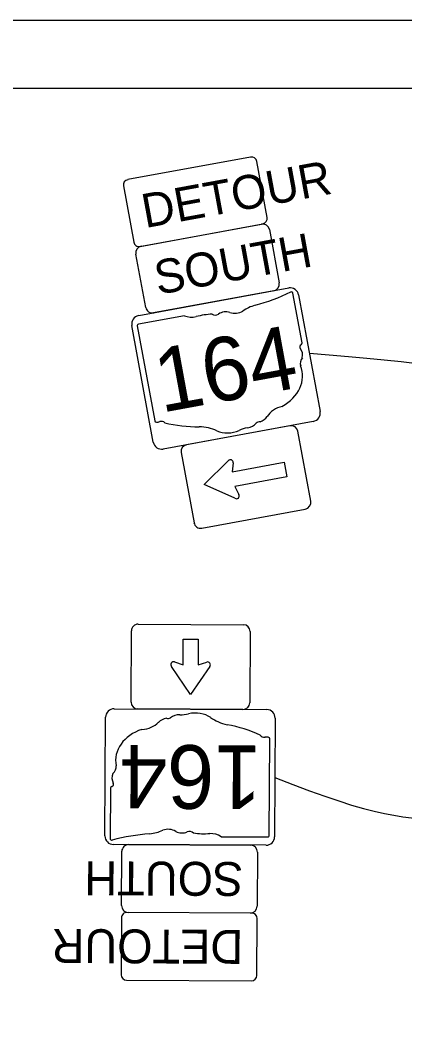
# Model space of a CAD drawing. Extents: x -202 to 1556, y 0 to 676.
# Drawn here: x 356.1 to 412.8, y 289.7 to 440 of the extents above; entities that cross this region are included whole.
import ezdxf

# ---------------------------------------------------------------- set-up
doc = ezdxf.new("R2010")
doc.units = 0
for name, color, linetype in [('GM_X_Minor_Lake', 7, 'Continuous'), ('GM_X_Minor_Lake_Text', 7, 'Continuous'), ('SH_Border', 7, 'Continuous'), ('SH_Cut_Line', 7, 'Continuous'), ('SH_Data', 7, 'Continuous')]:
    doc.layers.add(name, color=color, linetype=linetype)

msp = doc.modelspace()

# ---------------------------------------------------------------- linework, layer by layer
at = {"layer": 'GM_X_Minor_Lake'}
for p, q in [((373.97, 406.72), (391.67, 409.98)), ((392.84, 409.17), (394.29, 401.31)), ((374.62, 397.69), (373.17, 405.56)), ((393.48, 400.14), (375.78, 396.89)), ((397.66, 392.45), (396.31, 399.77)), ((380.31, 396.47), (373.55, 395.23)), ((373.37, 394.95), (375.95, 380.95)), ((397.66, 392.45), (397.66, 392.45)), ((373.51, 350.99), (389.01, 350.91)), ((372.45, 339.5), (372.5, 350)), ((380.14, 345.02), (380.15, 348.77)), ((380.15, 348.77), (382.34, 348.76)), ((382.34, 348.76), (382.32, 345.01)), ((390, 349.91), (389.95, 339.41)), ((381.21, 340.64), (378.43, 344.74)), ((378.85, 345.43), (380.14, 345.02)), ((384.07, 344.77), (381.21, 340.64)), ((382.32, 345.01), (383.61, 345.4)), ((388.94, 338.41), (373.44, 338.5)), ((392.82, 319.87), (392.89, 334.1)), ((369.42, 326.84), (369.38, 319.39)), ((369.42, 326.83), (369.42, 326.84)), ((385.72, 319.66), (392.59, 319.62)), ((371.04, 309.51), (371.09, 317.51)), ((372.09, 318.5), (390.09, 318.41)), ((391.09, 317.4), (391.04, 309.4)), ((390.04, 308.41), (372.04, 308.5))]:
    msp.add_line(p, q, dxfattribs=at)
for points in [[(390.06, 419.85), (371.96, 416.52)], [(392.51, 410.94), (390.99, 419.21)], [(371.32, 415.59), (372.84, 407.33)], [(373.77, 406.68), (391.87, 410.01)], [(373.57, 396.48), (395.7, 400.55)], [(397.15, 399.55), (400.32, 382.33)], [(375.73, 377.81), (372.56, 395.02)], [(399.31, 380.88), (377.19, 376.81)], [(369.94, 338.51), (392.44, 338.4)], [(368.6, 319.77), (368.69, 337.27)], [(393.69, 337.14), (393.6, 319.64)], [(392.34, 318.4), (369.84, 318.51)], [(390.24, 308.41), (371.84, 308.5)], [(371.03, 307.71), (370.99, 299.31)], [(390.99, 299.2), (391.03, 307.6)], [(371.79, 298.5), (390.19, 298.41)]]:
    msp.add_lwpolyline(points, dxfattribs=at)
for centre, radius, start, end in [((390.21, 419.06), 0.8, 10.4238, 100.4238), ((372.11, 415.73), 0.8, 100.4238, 190.4238), ((391.73, 410.8), 0.8, 280.4238, 10.4238), ((391.85, 408.99), 1, 10.4238, 100.4238), ((373.63, 407.47), 0.8, 190.4238, 280.4238), ((374.15, 405.74), 1, 100.4238, 190.4238), ((393.3, 401.13), 1, 280.4238, 10.4238), ((395.92, 399.32), 1.25, 10.4238, 100.4238), ((375.6, 397.87), 1, 190.4238, 280.4238), ((373.79, 395.25), 1.25, 100.4238, 190.4238), ((399.09, 382.11), 1.25, 280.4238, 10.4238), ((376.96, 378.04), 1.25, 190.4238, 280.4238), ((373.5, 349.99), 1, 89.7036, 179.7036), ((389, 349.91), 1, 359.7036, 89.7036), ((378.73, 345.03), 0.417, 72.499, 224.7132), ((383.73, 345), 0.417, 325.1148, 106.9082), ((369.94, 337.26), 1.25, 89.7036, 179.7036), ((373.45, 339.49), 1, 179.7036, 269.7036), ((388.95, 339.41), 1, 269.7036, 359.7036), ((392.44, 337.15), 1.25, 359.7036, 89.7036), ((369.85, 319.76), 1.25, 179.7036, 269.7036), ((392.35, 319.65), 1.25, 269.7036, 359.7036), ((372.09, 317.5), 1, 89.7036, 179.7036), ((390.09, 317.41), 1, 359.7036, 89.7036), ((371.83, 307.7), 0.8, 89.7036, 179.7036), ((372.04, 309.5), 1, 179.7036, 269.7036), ((390.04, 309.41), 1, 269.7036, 359.7036), ((390.23, 307.61), 0.8, 359.7036, 89.7036), ((371.79, 299.3), 0.8, 179.7036, 269.7036), ((390.19, 299.21), 0.8, 269.7036, 359.7036)]:
    msp.add_arc(centre, radius, start, end, dxfattribs=at)
for centre, major_axis, start_param, end_param in [((384.66, 417), (24.44, 4.5), 4.814394, 5.042369), ((396.05, 399.76), (0.257, 0.047), 6.141152, 7.989035), ((384.22, 389.07), (9.3, 1.71), 1.404758, 1.657858), ((384.91, 397.17), (0.747, 0.137), 3.836095, 5.185415), ((386.3, 395.76), (1.55, 0.29), 0.950623, 2.079405), ((387.9, 398.35), (1.87, 0.34), 4.081561, 5.145723), ((392.07, 394.22), (4.92, 0.9), 1.699011, 2.107814), ((373.63, 395.02), (0.267, 0.049), 1.712693, 3.28349), ((381.61, 398.39), (2.59, 0.48), 4.042523, 4.731795), ((397.7, 391.9), (0.397, 0.073), 1.883978, 3.671073), ((397.39, 392.37), (0.275, 0.051), 5.05454, 6.418171), ((395.34, 390.51), (2.38, 0.44), 5.934695, 6.695948), ((399.14, 389.56), (1.73, 0.32), 2.387724, 3.262537), ((391.55, 387.2), (6.11, 1.12), 5.101752, 6.440018), ((395.46, 380.48), (3.35, 0.62), 1.647645, 2.488434), ((376.22, 380.97), (0.269, 0.05), 3.00124, 4.508301), ((376, 382.41), (2.06, 0.38), 4.665946, 4.897461), ((376.82, 380.28), (0.741, 0.136), 0.519207, 1.627899), ((383.87, 394.57), (17.65, 3.25), 4.195997, 4.488961), ((389.38, 381.43), (1.87, 0.34), 4.691044, 5.507374), ((391.32, 380.39), (0.526, 0.097), 1.147584, 2.315152), ((390.74, 382.27), (1.98, 0.36), 4.937069, 5.64225), ((381.93, 375.55), (5.52, 1.02), 0.823519, 1.323587), ((386.91, 382.06), (3.5, 0.64), 4.026481, 4.996735), ((389.82, 377.59), (2.88, 0.53), 1.495662, 1.94098), ((378.11, 335.55), (-2.01, 0.01), 4.937069, 5.64225), ((377.89, 337.51), (-0.535, 0.003), 1.147584, 2.315152), ((379.6, 336.12), (-1.9, 0.01), 4.691044, 5.507374), ((379.88, 339.98), (-2.93, 0.02), 1.495662, 1.94098), ((381.92, 335.05), (-3.56, 0.02), 4.026481, 4.996735), ((388.02, 340.52), (-5.62, 0.03), 0.823519, 1.323587), ((376.39, 330.86), (-6.22, 0.03), 5.101752, 6.440018), ((373.81, 338.19), (-3.4, 0.02), 1.647645, 2.488434), ((382.57, 322.19), (-17.95, 0.09), 4.195997, 4.488961), ((392.16, 334.92), (-0.754, 0.004), 0.519207, 1.627899), ((392.57, 332.67), (-2.09, 0.01), 4.665946, 4.897461), ((392.62, 334.13), (-0.274, 0.001), 3.00124, 4.508301), ((368.5, 329.96), (-1.76, 0.01), 2.387724, 3.262537), ((372.05, 328.31), (-2.42, 0.01), 5.934695, 6.695948), ((369.69, 326.86), (-0.279, 0.001), 5.05454, 6.418171), ((369.48, 327.38), (-0.404, 0.002), 1.883978, 3.671073), ((377.63, 300.3), (-24.85, 0.13), 4.814394, 5.042369), ((374.58, 324.06), (-5, 0.03), 1.699011, 2.107814), ((377.91, 319.23), (-1.9, 0.01), 4.081561, 5.145723), ((379.96, 321.47), (-1.58, 0.01), 0.950623, 2.079405), ((381.07, 319.82), (-0.76, 0.004), 3.836095, 5.185415), ((383.26, 327.66), (-9.45, 0.05), 1.404758, 1.657858), ((384.08, 318.02), (-2.63, 0.01), 4.042523, 4.731795), ((369.64, 319.36), (-0.261, 0.001), 6.141152, 7.989035), ((392.55, 319.84), (-0.272, 0.001), 1.712693, 3.28349)]:
    msp.add_ellipse(centre, major_axis=major_axis, ratio=0.8, start_param=start_param, end_param=end_param, dxfattribs=at)
at = {"layer": 'GM_X_Minor_Lake_Text'}
for p, q in [((395.87, 380.25), (380.63, 377.44)), ((398.94, 369.12), (397.04, 379.44)), ((379.83, 376.28), (381.73, 365.95)), ((383.23, 371.57), (386.79, 375.11)), ((387.34, 373.43), (395.02, 374.85)), ((387.5, 374.77), (387.34, 373.43)), ((395.02, 374.85), (395.42, 372.69)), ((395.42, 372.69), (387.74, 371.28)), ((387.75, 369.56), (383.23, 371.57)), ((387.74, 371.28), (388.36, 370.09)), ((382.89, 365.15), (398.13, 367.95))]:
    msp.add_line(p, q, dxfattribs=at)
for centre, radius, start, end in [((396.05, 379.26), 1, 10.4238, 100.4238), ((380.81, 376.46), 1, 100.4238, 190.4238), ((387.08, 374.82), 0.417, 353.2192, 135.0126), ((387.99, 369.9), 0.417, 235.4143, 27.6284), ((397.95, 368.94), 1, 280.4238, 10.4238), ((382.71, 366.13), 1, 190.4238, 280.4238)]:
    msp.add_arc(centre, radius, start, end, dxfattribs=at)
at = {"layer": 'SH_Border'}
msp.add_lwpolyline([(30, 430), (670, 430), (670, 10), (30, 10)], close=True, dxfattribs=at)
at = {"layer": 'SH_Cut_Line'}
msp.add_lwpolyline([(0, 0), (680, 0), (680, 440), (0, 440)], close=True, dxfattribs=at)
at = {"layer": 'SH_Data'}
for points in [[(398.73, 390.94), (430.7, 388.56), (452.83, 380.39), (474.4, 358.12), (490.52, 340.72), (506.58, 327.55)], [(393.64, 328.39), (408.52, 322.46), (417.67, 322.03), (444.96, 322.07), (486.87, 322.04), (499.46, 315.2)], [(404.64, 246.73), (424.34, 248.87), (437.23, 257.61), (458.97, 274.11), (492.42, 299.36), (506.59, 301.5)]]:
    msp.add_open_spline(points, degree=3, dxfattribs=at)

# ---------------------------------------------------------------- texts
at = {"layer": 'GM_X_Minor_Lake'}
for s, height, rotation, p in [('DETOUR', 5, 10.4238, (374.53, 409.37)), ('SOUTH', 5, 10.4238, (376.4, 399.54)), ('164', 9.375, 10.4238, (376.89, 382.14)), ('164', 9.375, 179.7036, (391.74, 333.1)), ('SOUTH', 5, 179.7036, (388.99, 315.92)), ('DETOUR', 5, 179.7036, (388.99, 305.91))]:
    msp.add_text(s, height=height, rotation=rotation, dxfattribs=at).set_placement(p)

doc.saveas('drawing.dxf')
